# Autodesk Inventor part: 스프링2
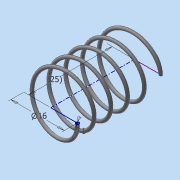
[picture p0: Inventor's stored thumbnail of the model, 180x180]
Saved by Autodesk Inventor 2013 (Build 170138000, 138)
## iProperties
Created: 2015-11
Part Number: 스프링2
Material: 강철, 탄소
Document SubType Name: Modeling
Designer: dgall
Density: 7.87 g/cm^3
Mass: 1.48801 g
Surface Area: 7.67123 cm^2
Volume: 0.189074 cm^3
Author: dgall
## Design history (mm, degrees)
sketch "스케치1"
  geometry: L1 (8, 0)-(0, 0); L2 (0, 0)-(0, 26); L3 (0, 26)-(8, 26); C1 r 0.5 at (8, 0)
  constraints: 6 end point, 1 centre point, 1 coincident, 1 horizontal, 1 parallel, 1 perpendicular, 1 vertical alignment
  dimensions: "d5" = 16 diameter of L1.start L2; "d7" = 26 distance of L1.end L2.end (derived); "d8" = 1 diameter of C1
feature "코일1" pitch "d9" = 10; turns "d11" = 5; dims "d10" = 26 (= d7), "d12" = 0, angle "d13" = 90 deg, angle "d14" = 90 deg, "d15" = 0, "d16" = 0
sketch "스케치2"
  geometry: L1 (-10, 0)-(10, 0); L2 (10, 0)-(10, -5); L3 (10, -5)-(-10, -5); L4 (-10, -5)-(-10, 0); L5 (-10, 30)-(10, 30); L6 (10, 30)-(10, 25); L7 (10, 25)-(-10, 25); L8 (-10, 25)-(-10, 30); 4 further points
  constraints: 16 end point, 4 parallel, 3 midpoint, 2 horizontal, 2 perpendicular, 1 coincident, 1 vertical alignment
  dimensions: "d17" = 25 distance between parallel lines of L7 L1; "d18" = 5 distance of L7.end L5.start; "d19" = 5 distance of L3.end L1.start; "d20" = 20 distance of L2.end L3.end; "d21" = 20 distance of L5.start L5.end
extrude "돌출1" cut sketch "스케치2" stored distance "d22" = 30; taper "d23" = 0 deg
node "솔리드1"
